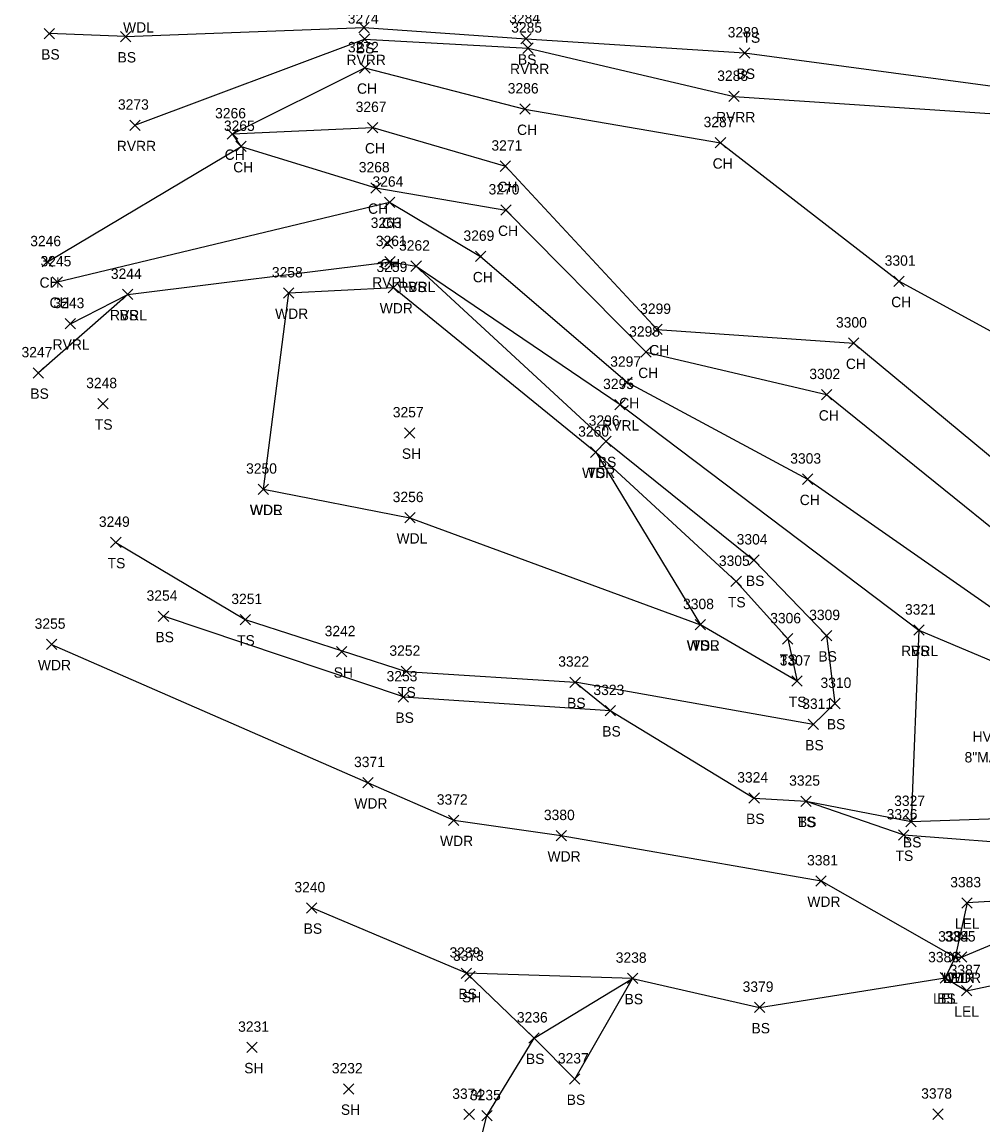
# Model space of a CAD drawing. Extents: x 1601151 to 1602912, y 499508 to 501770.
# Drawn here: x 1601296.9 to 1601482.2, y 500596.8 to 500809.5 of the extents above; entities that cross this region are included whole.
import ezdxf

# ---------------------------------------------------------------- set-up
doc = ezdxf.new("R2010")
doc.units = 0
for name, color, linetype in [('C_A', 7, 'Continuous'), ('C_C', 7, 'Continuous'), ('L_A', 7, 'Continuous'), ('L_I', 7, 'Continuous'), ('L_TIC', 7, 'Continuous'), ('LARO', 7, 'Continuous'), ('LAWA', 7, 'Continuous'), ('LAWE', 7, 'Continuous'), ('LDEFAULT', 7, 'Continuous'), ('LELB', 7, 'Continuous')]:
    doc.layers.add(name, color=color, linetype=linetype)

msp = doc.modelspace()

# ---------------------------------------------------------------- linework, layer by layer
at = {"layer": 'L_TIC'}
for points in [[(1601361.81, 500807.47), (1601363.81, 500809.47)], [(1601363.81, 500807.47), (1601361.81, 500809.47)], [(1601301.11, 500806.28), (1601303.11, 500808.28)], [(1601303.11, 500806.28), (1601301.11, 500808.28)], [(1601315.84, 500805.72), (1601317.84, 500807.72)], [(1601317.84, 500805.72), (1601315.84, 500807.72)], [(1601315.84, 500805.72), (1601317.84, 500807.72)], [(1601317.84, 500805.72), (1601315.84, 500807.72)], [(1601361.93, 500805.22), (1601363.93, 500807.22)], [(1601363.93, 500805.22), (1601361.93, 500807.22)], [(1601393.06, 500805.3), (1601395.06, 500807.3)], [(1601395.06, 500805.3), (1601393.06, 500807.3)], [(1601393.46, 500803.48), (1601395.46, 500805.48)], [(1601395.46, 500803.48), (1601393.46, 500805.48)], [(1601435.22, 500802.55), (1601437.22, 500804.55)], [(1601437.22, 500802.55), (1601435.22, 500804.55)], [(1601361.97, 500799.69), (1601363.97, 500801.69)], [(1601363.97, 500799.69), (1601361.97, 500801.69)], [(1601433.19, 500794.17), (1601435.19, 500796.17)], [(1601435.19, 500794.17), (1601433.19, 500796.17)], [(1601392.84, 500791.74), (1601394.84, 500793.74)], [(1601394.84, 500791.74), (1601392.84, 500793.74)], [(1601317.62, 500788.62), (1601319.62, 500790.62)], [(1601319.62, 500788.62), (1601317.62, 500790.62)], [(1601363.5, 500788.17), (1601365.5, 500790.17)], [(1601365.5, 500788.17), (1601363.5, 500790.17)], [(1601336.45, 500786.94), (1601338.45, 500788.94)], [(1601338.45, 500786.94), (1601336.45, 500788.94)], [(1601336.45, 500786.94), (1601338.45, 500788.94)], [(1601338.45, 500786.94), (1601336.45, 500788.94)], [(1601338.09, 500784.52), (1601340.09, 500786.52)], [(1601340.09, 500784.52), (1601338.09, 500786.52)], [(1601338.09, 500784.52), (1601340.09, 500786.52)], [(1601340.09, 500784.52), (1601338.09, 500786.52)], [(1601430.56, 500785.24), (1601432.56, 500787.24)], [(1601432.56, 500785.24), (1601430.56, 500787.24)], [(1601389.07, 500780.72), (1601391.07, 500782.72)], [(1601391.07, 500780.72), (1601389.07, 500782.72)], [(1601364.11, 500776.53), (1601366.11, 500778.53)], [(1601366.11, 500776.53), (1601364.11, 500778.53)], [(1601366.74, 500773.76), (1601368.74, 500775.76)], [(1601368.74, 500773.76), (1601366.74, 500775.76)], [(1601389.18, 500772.26), (1601391.18, 500774.26)], [(1601391.18, 500772.26), (1601389.18, 500774.26)], [(1601366.4, 500765.81), (1601368.4, 500767.81)], [(1601368.4, 500765.81), (1601366.4, 500767.81)], [(1601384.3, 500763.32), (1601386.3, 500765.32)], [(1601386.3, 500763.32), (1601384.3, 500765.32)], [(1601300.76, 500762.28), (1601302.76, 500764.28)], [(1601302.76, 500762.28), (1601300.76, 500764.28)], [(1601366.83, 500762.3), (1601368.83, 500764.3)], [(1601368.83, 500762.3), (1601366.83, 500764.3)], [(1601371.87, 500761.43), (1601373.87, 500763.43)], [(1601373.87, 500761.43), (1601371.87, 500763.43)], [(1601371.87, 500761.43), (1601373.87, 500763.43)], [(1601373.87, 500761.43), (1601371.87, 500763.43)], [(1601302.68, 500758.4), (1601304.68, 500760.4)], [(1601304.68, 500758.4), (1601302.68, 500760.4)], [(1601465, 500758.52), (1601467, 500760.52)], [(1601467, 500758.52), (1601465, 500760.52)], [(1601347.3, 500756.26), (1601349.3, 500758.26)], [(1601349.3, 500756.26), (1601347.3, 500758.26)], [(1601367.48, 500757.31), (1601369.48, 500759.31)], [(1601369.48, 500757.31), (1601367.48, 500759.31)], [(1601316.25, 500755.98), (1601318.25, 500757.98)], [(1601318.25, 500755.98), (1601316.25, 500757.98)], [(1601316.25, 500755.98), (1601318.25, 500757.98)], [(1601318.25, 500755.98), (1601316.25, 500757.98)], [(1601305.18, 500750.33), (1601307.18, 500752.33)], [(1601307.18, 500750.33), (1601305.18, 500752.33)], [(1601418.33, 500749.23), (1601420.33, 500751.23)], [(1601420.33, 500749.23), (1601418.33, 500751.23)], [(1601456.25, 500746.59), (1601458.25, 500748.59)], [(1601458.25, 500746.59), (1601456.25, 500748.59)], [(1601416.2, 500744.85), (1601418.2, 500746.85)], [(1601418.2, 500744.85), (1601416.2, 500746.85)], [(1601299.02, 500740.85), (1601301.02, 500742.85)], [(1601301.02, 500740.85), (1601299.02, 500742.85)], [(1601412.55, 500739.04), (1601414.55, 500741.04)], [(1601414.55, 500739.04), (1601412.55, 500741.04)], [(1601311.49, 500734.9), (1601313.49, 500736.9)], [(1601313.49, 500734.9), (1601311.49, 500736.9)], [(1601451.03, 500736.65), (1601453.03, 500738.65)], [(1601453.03, 500736.65), (1601451.03, 500738.65)], [(1601411.18, 500734.73), (1601413.18, 500736.73)], [(1601413.18, 500734.73), (1601411.18, 500736.73)], [(1601370.62, 500729.27), (1601372.62, 500731.27)], [(1601372.62, 500729.27), (1601370.62, 500731.27)], [(1601408.45, 500727.66), (1601410.45, 500729.66)], [(1601410.45, 500727.66), (1601408.45, 500729.66)], [(1601406.51, 500725.56), (1601408.51, 500727.56)], [(1601408.51, 500725.56), (1601406.51, 500727.56)], [(1601406.51, 500725.56), (1601408.51, 500727.56)], [(1601408.51, 500725.56), (1601406.51, 500727.56)], [(1601447.35, 500720.35), (1601449.35, 500722.35)], [(1601449.35, 500720.35), (1601447.35, 500722.35)], [(1601342.42, 500718.41), (1601344.42, 500720.41)], [(1601344.42, 500718.41), (1601342.42, 500720.41)], [(1601342.42, 500718.41), (1601344.42, 500720.41)], [(1601344.42, 500718.41), (1601342.42, 500720.41)], [(1601370.66, 500712.92), (1601372.66, 500714.92)], [(1601372.66, 500712.92), (1601370.66, 500714.92)], [(1601313.95, 500708.15), (1601315.95, 500710.15)], [(1601315.95, 500708.15), (1601313.95, 500710.15)], [(1601437.02, 500704.75), (1601439.02, 500706.75)], [(1601439.02, 500704.75), (1601437.02, 500706.75)], [(1601433.58, 500700.62), (1601435.58, 500702.62)], [(1601435.58, 500700.62), (1601433.58, 500702.62)], [(1601323.14, 500693.9), (1601325.14, 500695.9)], [(1601325.14, 500693.9), (1601323.14, 500695.9)], [(1601338.92, 500693.26), (1601340.92, 500695.26)], [(1601340.92, 500693.26), (1601338.92, 500695.26)], [(1601426.68, 500692.28), (1601428.68, 500694.28)], [(1601428.68, 500692.28), (1601426.68, 500694.28)], [(1601426.68, 500692.28), (1601428.68, 500694.28)], [(1601428.68, 500692.28), (1601426.68, 500694.28)], [(1601426.68, 500692.28), (1601428.68, 500694.28)], [(1601428.68, 500692.28), (1601426.68, 500694.28)], [(1601451, 500690.17), (1601453, 500692.17)], [(1601453, 500690.17), (1601451, 500692.17)], [(1601468.83, 500691.23), (1601470.83, 500693.23)], [(1601470.83, 500691.23), (1601468.83, 500693.23)], [(1601468.83, 500691.23), (1601470.83, 500693.23)], [(1601470.83, 500691.23), (1601468.83, 500693.23)], [(1601301.55, 500688.49), (1601303.55, 500690.49)], [(1601303.55, 500688.49), (1601301.55, 500690.49)], [(1601443.54, 500689.55), (1601445.54, 500691.55)], [(1601445.54, 500689.55), (1601443.54, 500691.55)], [(1601357.48, 500687.06), (1601359.48, 500689.06)], [(1601359.48, 500687.06), (1601357.48, 500689.06)], [(1601369.97, 500683.28), (1601371.97, 500685.28)], [(1601371.97, 500683.28), (1601369.97, 500685.28)], [(1601402.53, 500681.19), (1601404.53, 500683.19)], [(1601404.53, 500681.19), (1601402.53, 500683.19)], [(1601445.32, 500681.4), (1601447.32, 500683.4)], [(1601447.32, 500681.4), (1601445.32, 500683.4)], [(1601369.42, 500678.35), (1601371.42, 500680.35)], [(1601371.42, 500678.35), (1601369.42, 500680.35)], [(1601369.42, 500678.35), (1601371.42, 500680.35)], [(1601371.42, 500678.35), (1601369.42, 500680.35)], [(1601409.31, 500675.71), (1601411.31, 500677.71)], [(1601411.31, 500675.71), (1601409.31, 500677.71)], [(1601409.31, 500675.71), (1601411.31, 500677.71)], [(1601411.31, 500675.71), (1601409.31, 500677.71)], [(1601452.62, 500677.08), (1601454.62, 500679.08)], [(1601454.62, 500677.08), (1601452.62, 500679.08)], [(1601448.45, 500673.04), (1601450.45, 500675.04)], [(1601450.45, 500673.04), (1601448.45, 500675.04)], [(1601362.58, 500661.81), (1601364.58, 500663.81)], [(1601364.58, 500661.81), (1601362.58, 500663.81)], [(1601437.05, 500658.84), (1601439.05, 500660.84)], [(1601439.05, 500658.84), (1601437.05, 500660.84)], [(1601447.06, 500658.23), (1601449.06, 500660.23)], [(1601449.06, 500658.23), (1601447.06, 500660.23)], [(1601447.06, 500658.23), (1601449.06, 500660.23)], [(1601449.06, 500658.23), (1601447.06, 500660.23)], [(1601379.11, 500654.57), (1601381.11, 500656.57)], [(1601381.11, 500654.57), (1601379.11, 500656.57)], [(1601467.31, 500654.32), (1601469.31, 500656.32)], [(1601469.31, 500654.32), (1601467.31, 500656.32)], [(1601467.31, 500654.32), (1601469.31, 500656.32)], [(1601469.31, 500654.32), (1601467.31, 500656.32)], [(1601399.84, 500651.59), (1601401.84, 500653.59)], [(1601401.84, 500651.59), (1601399.84, 500653.59)], [(1601465.91, 500651.72), (1601467.91, 500653.72)], [(1601467.91, 500651.72), (1601465.91, 500653.72)], [(1601449.95, 500642.85), (1601451.95, 500644.85)], [(1601451.95, 500642.85), (1601449.95, 500644.85)], [(1601351.73, 500637.66), (1601353.73, 500639.66)], [(1601353.73, 500637.66), (1601351.73, 500639.66)], [(1601478.12, 500638.62), (1601480.12, 500640.62)], [(1601480.12, 500638.62), (1601478.12, 500640.62)], [(1601475.8, 500628.17), (1601477.8, 500630.17)], [(1601477.8, 500628.17), (1601475.8, 500630.17)], [(1601475.8, 500628.17), (1601477.8, 500630.17)], [(1601477.8, 500628.17), (1601475.8, 500630.17)], [(1601477.07, 500628.17), (1601479.07, 500630.17)], [(1601479.07, 500628.17), (1601477.07, 500630.17)], [(1601381.57, 500625.06), (1601383.57, 500627.06)], [(1601383.57, 500625.06), (1601381.57, 500627.06)], [(1601381.57, 500625.06), (1601383.57, 500627.06)], [(1601383.57, 500625.06), (1601381.57, 500627.06)], [(1601382.23, 500624.44), (1601384.23, 500626.44)], [(1601384.23, 500624.44), (1601382.23, 500626.44)], [(1601473.92, 500624.17), (1601475.92, 500626.17)], [(1601475.92, 500624.17), (1601473.92, 500626.17)], [(1601473.92, 500624.17), (1601475.92, 500626.17)], [(1601475.92, 500624.17), (1601473.92, 500626.17)], [(1601413.62, 500624.07), (1601415.62, 500626.07)], [(1601415.62, 500624.07), (1601413.62, 500626.07)], [(1601413.62, 500624.07), (1601415.62, 500626.07)], [(1601415.62, 500624.07), (1601413.62, 500626.07)], [(1601413.62, 500624.07), (1601415.62, 500626.07)], [(1601415.62, 500624.07), (1601413.62, 500626.07)], [(1601478.02, 500621.68), (1601480.02, 500623.68)], [(1601480.02, 500621.68), (1601478.02, 500623.68)], [(1601438.1, 500618.46), (1601440.1, 500620.46)], [(1601440.1, 500618.46), (1601438.1, 500620.46)], [(1601394.6, 500612.55), (1601396.6, 500614.55)], [(1601396.6, 500612.55), (1601394.6, 500614.55)], [(1601394.6, 500612.55), (1601396.6, 500614.55)], [(1601396.6, 500612.55), (1601394.6, 500614.55)], [(1601394.6, 500612.55), (1601396.6, 500614.55)], [(1601396.6, 500612.55), (1601394.6, 500614.55)], [(1601340.22, 500610.76), (1601342.22, 500612.76)], [(1601342.22, 500610.76), (1601340.22, 500612.76)], [(1601402.46, 500604.65), (1601404.46, 500606.65)], [(1601404.46, 500604.65), (1601402.46, 500606.65)], [(1601358.86, 500602.74), (1601360.86, 500604.74)], [(1601360.86, 500602.74), (1601358.86, 500604.74)], [(1601382.09, 500597.82), (1601384.09, 500599.82)], [(1601384.09, 500597.82), (1601382.09, 500599.82)], [(1601385.5, 500597.56), (1601387.5, 500599.56)], [(1601387.5, 500597.56), (1601385.5, 500599.56)], [(1601472.52, 500597.87), (1601474.52, 500599.87)], [(1601474.52, 500597.87), (1601472.52, 500599.87)]]:
    msp.add_lwpolyline(points, dxfattribs=at)
at = {"layer": 'LARO'}
msp.add_lwpolyline([(1601488.82, 500656.03), (1601493.86, 500650.7), (1601495.52, 500640.59), (1601479.12, 500639.62), (1601476.8, 500629.17), (1601474.92, 500625.17), (1601479.02, 500622.68), (1601491.71, 500625.34), (1601500.4, 500627.93), (1601508.54, 500628.04)], dxfattribs=at)
at = {"layer": 'LAWA'}
for points in [[(1601343.42, 500719.41), (1601348.3, 500757.26), (1601368.48, 500758.31), (1601407.51, 500726.56), (1601427.68, 500693.28)], [(1601343.42, 500719.41), (1601371.66, 500713.92), (1601427.68, 500693.28)], [(1601302.55, 500689.49), (1601363.58, 500662.81), (1601380.11, 500655.57), (1601400.84, 500652.59), (1601450.95, 500643.85), (1601476.8, 500629.17), (1601478.07, 500629.17), (1601496.83, 500637), (1601499.44, 500638.01), (1601508.97, 500634.75), (1601512.57, 500627.47), (1601537.32, 500627.23), (1601563.93, 500612.63), (1601565.22, 500607.85), (1601579.08, 500591.88), (1601571.6, 500572.54), (1601570.48, 500566.05)]]:
    msp.add_lwpolyline(points, dxfattribs=at)
at = {"layer": 'LAWE'}
for points in [[(1601318.62, 500789.62), (1601362.93, 500806.22), (1601394.46, 500804.48), (1601434.19, 500795.17), (1601527.96, 500788.91), (1601546.38, 500778.25), (1601558, 500777.29), (1601574.08, 500771.8), (1601598.01, 500757.12), (1601667.95, 500738.14), (1601705.28, 500715.12), (1601735.85, 500687.88), (1601768.33, 500671.26), (1601783.77, 500659.22)], [(1601306.18, 500751.33), (1601317.25, 500756.98), (1601367.83, 500763.3), (1601372.87, 500762.43), (1601412.18, 500735.73), (1601469.83, 500692.23), (1601501.36, 500678.91), (1601577.08, 500648.29), (1601592.03, 500648.06), (1601605.35, 500652.04), (1601618.61, 500651.39), (1601650.85, 500649.25), (1601686.37, 500649.48), (1601701.52, 500650.2), (1601728.46, 500647.17), (1601756.56, 500648.67), (1601769.4, 500643.2)]]:
    msp.add_lwpolyline(points, dxfattribs=at)
at = {"layer": 'LDEFAULT'}
for points in [[(1601337.45, 500787.94), (1601362.97, 500800.69), (1601393.84, 500792.74), (1601431.56, 500786.24), (1601466, 500759.52), (1601526, 500726.82), (1601566.27, 500697.9), (1601580.09, 500695.39), (1601593.87, 500695.15), (1601641.19, 500685.49), (1601672.03, 500699.21), (1601695.98, 500708.01), (1601703.42, 500706.03), (1601734.4, 500680.19), (1601767.36, 500664.87), (1601779.68, 500657.31)], [(1601339.09, 500785.52), (1601337.45, 500787.94), (1601364.5, 500789.17), (1601390.07, 500781.72), (1601419.33, 500750.23), (1601457.25, 500747.59), (1601513.71, 500700.8), (1601568.04, 500687.18), (1601598.22, 500676.18), (1601647.03, 500668.88), (1601695.93, 500672.79), (1601756.55, 500665.64), (1601778.58, 500654.09)], [(1601301.76, 500763.28), (1601339.09, 500785.52), (1601365.11, 500777.53), (1601390.18, 500773.26), (1601417.2, 500745.85), (1601452.03, 500737.65), (1601508.9, 500691.77), (1601569.64, 500683.25), (1601580.39, 500680.59), (1601586.29, 500672.56), (1601600.69, 500667.89), (1601646.7, 500657.93), (1601688.58, 500663.11)], [(1601303.68, 500759.4), (1601367.74, 500774.76), (1601385.3, 500764.32), (1601413.55, 500740.04), (1601448.35, 500721.35), (1601503.88, 500682.57), (1601578.22, 500651.86), (1601591.68, 500650.62), (1601603.79, 500656.64), (1601648.59, 500654.17), (1601682.93, 500659.64), (1601726.96, 500654.03), (1601736.69, 500654.19), (1601757.22, 500650.94), (1601774.12, 500647.76)]]:
    msp.add_lwpolyline(points, dxfattribs=at)
at = {"layer": 'LELB'}
for points in [[(1601316.84, 500806.72), (1601302.11, 500807.28)], [(1601316.84, 500806.72), (1601362.81, 500808.47), (1601394.06, 500806.3), (1601436.22, 500803.55), (1601489.34, 500796.43), (1601527.96, 500788.91), (1601544.19, 500785.17)], [(1601372.87, 500762.43), (1601409.45, 500728.66), (1601438.02, 500705.75), (1601452, 500691.17), (1601453.62, 500678.08), (1601449.45, 500674.04), (1601403.53, 500682.19), (1601410.31, 500676.71)], [(1601317.25, 500756.98), (1601300.02, 500741.85)], [(1601407.51, 500726.56), (1601434.58, 500701.62), (1601444.54, 500690.55), (1601446.32, 500682.4), (1601427.68, 500693.28)], [(1601314.95, 500709.15), (1601339.92, 500694.26), (1601370.97, 500684.28)], [(1601370.42, 500679.35), (1601324.14, 500694.9)], [(1601469.83, 500692.23), (1601468.31, 500655.32)], [(1601370.97, 500684.28), (1601403.53, 500682.19)], [(1601370.42, 500679.35), (1601410.31, 500676.71), (1601438.05, 500659.84), (1601448.06, 500659.23), (1601468.31, 500655.32), (1601488.82, 500656.03)], [(1601448.06, 500659.23), (1601466.91, 500652.72), (1601493.86, 500650.7)], [(1601395.6, 500613.55), (1601382.57, 500626.06), (1601352.73, 500638.66)], [(1601400.22, 500561.71), (1601389.46, 500565.78), (1601381.12, 500577.39), (1601386.5, 500598.56), (1601395.6, 500613.55), (1601414.62, 500625.07), (1601439.1, 500619.46), (1601474.92, 500625.17)], [(1601414.62, 500625.07), (1601382.57, 500626.06)], [(1601395.6, 500613.55), (1601403.46, 500605.65), (1601414.62, 500625.07)]]:
    msp.add_lwpolyline(points, dxfattribs=at)

# ---------------------------------------------------------------- texts
at = {"layer": 'C_A'}
msp.add_text('HVCTRL', height=2, dxfattribs=at).set_placement((1601480.18, 500670.71))
at = {"layer": 'C_C'}
msp.add_text('8"MAGHUB', height=2, dxfattribs=at).set_placement((1601478.63, 500666.71))
at = {"layer": 'L_A'}
for s, p in [('WDL', (1601316.34, 500807.49)), ('TS', (1601435.8, 500805.52)), ('BS', (1601361.25, 500803.47)), ('BS', (1601300.55, 500802.28)), ('BS', (1601315.28, 500801.72)), ('BS', (1601315.28, 500801.72)), ('RVRR', (1601359.44, 500801.22)), ('BS', (1601392.5, 500801.3)), ('RVRR', (1601390.97, 500799.48)), ('BS', (1601434.66, 500798.55)), ('CH', (1601361.46, 500795.69)), ('RVRR', (1601430.7, 500790.17)), ('CH', (1601392.33, 500787.74)), ('RVRR', (1601315.13, 500784.62)), ('CH', (1601362.99, 500784.17)), ('CH', (1601335.94, 500782.94)), ('CH', (1601335.94, 500782.94)), ('CH', (1601337.58, 500780.52)), ('CH', (1601337.58, 500780.52)), ('CH', (1601430.05, 500781.24)), ('CH', (1601388.56, 500776.72)), ('CH', (1601363.59, 500772.53)), ('CH', (1601366.23, 500769.76)), ('CH', (1601388.66, 500768.26)), ('CH', (1601365.89, 500761.81)), ('CH', (1601300.24, 500758.28)), ('RVRL', (1601364.39, 500758.3)), ('CH', (1601383.79, 500759.32)), ('RVRL', (1601369.44, 500757.43)), ('BS', (1601371.31, 500757.43)), ('CH', (1601302.16, 500754.4)), ('CH', (1601464.48, 500754.52)), ('RVRL', (1601313.82, 500751.98)), ('BS', (1601315.69, 500751.98)), ('WDR', (1601345.66, 500752.26)), ('WDR', (1601365.84, 500753.31)), ('RVRL', (1601302.75, 500746.33)), ('CH', (1601417.82, 500745.23)), ('CH', (1601455.74, 500742.59)), ('CH', (1601415.69, 500740.85)), ('BS', (1601298.46, 500736.85)), ('CH', (1601412.03, 500735.04)), ('CH', (1601450.51, 500732.65)), ('TS', (1601310.9, 500730.9)), ('RVRL', (1601408.75, 500730.73)), ('SH', (1601370.11, 500725.27)), ('BS', (1601407.89, 500723.66)), ('WDR', (1601404.87, 500721.56)), ('TS', (1601405.92, 500721.56)), ('CH', (1601446.84, 500716.35)), ('WDR', (1601340.78, 500714.41)), ('WDL', (1601340.83, 500714.41)), ('WDL', (1601369.08, 500708.92)), ('TS', (1601313.36, 500704.15)), ('BS', (1601436.46, 500700.75)), ('TS', (1601432.99, 500696.62)), ('BS', (1601322.58, 500689.9)), ('TS', (1601338.33, 500689.26)), ('WDR', (1601425.04, 500688.28)), ('WDL', (1601425.09, 500688.28)), ('TS', (1601426.09, 500688.28)), ('BS', (1601450.44, 500686.17)), ('RVRL', (1601466.4, 500687.23)), ('BS', (1601468.27, 500687.23)), ('WDR', (1601299.92, 500684.49)), ('TS', (1601442.95, 500685.55)), ('SH', (1601356.96, 500683.06)), ('TS', (1601369.38, 500679.28)), ('TS', (1601444.73, 500677.4)), ('BS', (1601401.97, 500677.19)), ('BS', (1601368.86, 500674.35)), ('BS', (1601368.86, 500674.35)), ('BS', (1601452.06, 500673.08)), ('BS', (1601408.76, 500671.71)), ('BS', (1601408.76, 500671.71)), ('BS', (1601447.89, 500669.04)), ('WDR', (1601360.94, 500657.81)), ('BS', (1601436.49, 500654.84)), ('TS', (1601446.47, 500654.23)), ('BS', (1601446.5, 500654.23)), ('WDR', (1601377.47, 500650.57)), ('BS', (1601466.75, 500650.32)), ('BS', (1601466.75, 500650.32)), ('WDR', (1601398.2, 500647.59)), ('TS', (1601465.32, 500647.72)), ('WDR', (1601448.31, 500638.85)), ('BS', (1601351.17, 500633.66)), ('LEL', (1601476.75, 500634.62)), ('WDR', (1601474.16, 500624.17)), ('LEL', (1601474.44, 500624.17)), ('WDR', (1601475.43, 500624.17)), ('BS', (1601381.01, 500621.06)), ('BS', (1601381.01, 500621.06)), ('SH', (1601381.71, 500620.44)), ('BS', (1601413.06, 500620.07)), ('BS', (1601413.06, 500620.07)), ('BS', (1601413.06, 500620.07)), ('LEL', (1601472.55, 500620.17)), ('BS', (1601473.36, 500620.17)), ('LEL', (1601476.66, 500617.68)), ('BS', (1601437.54, 500614.46)), ('BS', (1601394.04, 500608.55)), ('BS', (1601394.04, 500608.55)), ('BS', (1601394.04, 500608.55)), ('SH', (1601339.71, 500606.76)), ('SH', (1601358.35, 500598.74)), ('BS', (1601401.9, 500600.65))]:
    msp.add_text(s, height=2, dxfattribs=at).set_placement(p)
at = {"layer": 'L_I'}
for s, p in [('3274', (1601359.67, 500809.22)), ('3284', (1601390.8, 500809.3)), ('3285', (1601391.2, 500807.48)), ('3289', (1601432.95, 500806.55)), ('3272', (1601359.71, 500803.69)), ('3288', (1601430.93, 500798.17)), ('3286', (1601390.53, 500795.74)), ('3273', (1601315.36, 500792.62)), ('3267', (1601361.2, 500792.17)), ('3266', (1601334.09, 500790.94)), ('3266', (1601334.09, 500790.94)), ('3265', (1601335.79, 500788.52)), ('3265', (1601335.79, 500788.52)), ('3287', (1601428.3, 500789.24)), ('3271', (1601387.38, 500784.72)), ('3268', (1601361.8, 500780.53)), ('3264', (1601364.44, 500777.76)), ('3270', (1601386.83, 500776.26)), ('3263', (1601364.1, 500769.81)), ('3269', (1601381.99, 500767.32)), ('3246', (1601298.44, 500766.28)), ('3261', (1601365.09, 500766.3)), ('3262', (1601369.56, 500765.43)), ('3262', (1601369.56, 500765.43)), ('3245', (1601300.42, 500762.4)), ('3301', (1601463.23, 500762.52)), ('3258', (1601345.04, 500760.26)), ('3259', (1601365.21, 500761.31)), ('3244', (1601313.99, 500759.98)), ('3244', (1601313.99, 500759.98)), ('3243', (1601302.92, 500754.33)), ('3299', (1601416.06, 500753.23)), ('3300', (1601453.83, 500750.59)), ('3298', (1601413.94, 500748.85)), ('3247', (1601296.76, 500744.85)), ('3297', (1601410.29, 500743.04)), ('3302', (1601448.69, 500740.65)), ('3248', (1601309.23, 500738.9)), ('3295', (1601408.92, 500738.73)), ('3257', (1601368.36, 500733.27)), ('3296', (1601406.14, 500731.66)), ('3260', (1601404.11, 500729.56)), ('3260', (1601404.11, 500729.56)), ('3303', (1601445.01, 500724.35)), ('3250', (1601340.07, 500722.41)), ('3250', (1601340.07, 500722.41)), ('3256', (1601368.34, 500716.92)), ('3249', (1601311.68, 500712.15)), ('3304', (1601434.68, 500708.75)), ('3305', (1601431.25, 500704.62)), ('3254', (1601320.88, 500697.9)), ('3251', (1601337.22, 500697.26)), ('3308', (1601424.34, 500696.28)), ('3308', (1601424.34, 500696.28)), ('3308', (1601424.34, 500696.28)), ('3321', (1601467.14, 500695.23)), ('3321', (1601467.14, 500695.23)), ('3255', (1601299.29, 500692.49)), ('3306', (1601441.14, 500693.55)), ('3309', (1601448.66, 500694.17)), ('3242', (1601355.22, 500691.06)), ('3252', (1601367.71, 500687.28)), ('3322', (1601400.27, 500685.19)), ('3307', (1601442.98, 500685.4)), ('3253', (1601367.16, 500682.35)), ('3253', (1601367.16, 500682.35)), ('3323', (1601407.05, 500679.71)), ('3323', (1601407.05, 500679.71)), ('3310', (1601450.84, 500681.08)), ('3311', (1601447.32, 500677.04)), ('3371', (1601360.89, 500665.81)), ('3324', (1601434.79, 500662.84)), ('3325', (1601444.8, 500662.23)), ('3325', (1601444.8, 500662.23)), ('3372', (1601376.85, 500658.57)), ('3327', (1601465.05, 500658.32)), ('3327', (1601465.05, 500658.32)), ('3380', (1601397.5, 500655.59)), ('3326', (1601463.6, 500655.72)), ('3381', (1601448.26, 500646.85)), ('3240', (1601349.39, 500641.66)), ('3383', (1601475.86, 500642.62)), ('3384', (1601473.54, 500632.17)), ('3384', (1601473.54, 500632.17)), ('3385', (1601474.81, 500632.17)), ('3239', (1601379.3, 500629.06)), ('3239', (1601379.3, 500629.06)), ('3373', (1601379.97, 500628.44)), ('3238', (1601411.36, 500628.07)), ('3238', (1601411.36, 500628.07)), ('3238', (1601411.36, 500628.07)), ('3386', (1601471.6, 500628.17)), ('3386', (1601471.6, 500628.17)), ('3387', (1601475.76, 500625.68)), ('3379', (1601435.83, 500622.46)), ('3236', (1601392.29, 500616.55)), ('3236', (1601392.29, 500616.55)), ('3236', (1601392.29, 500616.55)), ('3231', (1601338.53, 500614.76)), ('3237', (1601400.2, 500608.65)), ('3232', (1601356.6, 500606.74)), ('3374', (1601379.83, 500601.82)), ('3235', (1601383.24, 500601.56)), ('3378', (1601470.26, 500601.87))]:
    msp.add_text(s, height=2, dxfattribs=at).set_placement(p)

doc.saveas('drawing.dxf')
